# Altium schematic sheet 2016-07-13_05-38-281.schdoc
size 227 x 113 mm; SheetNumber: 1; SheetTotal: 1
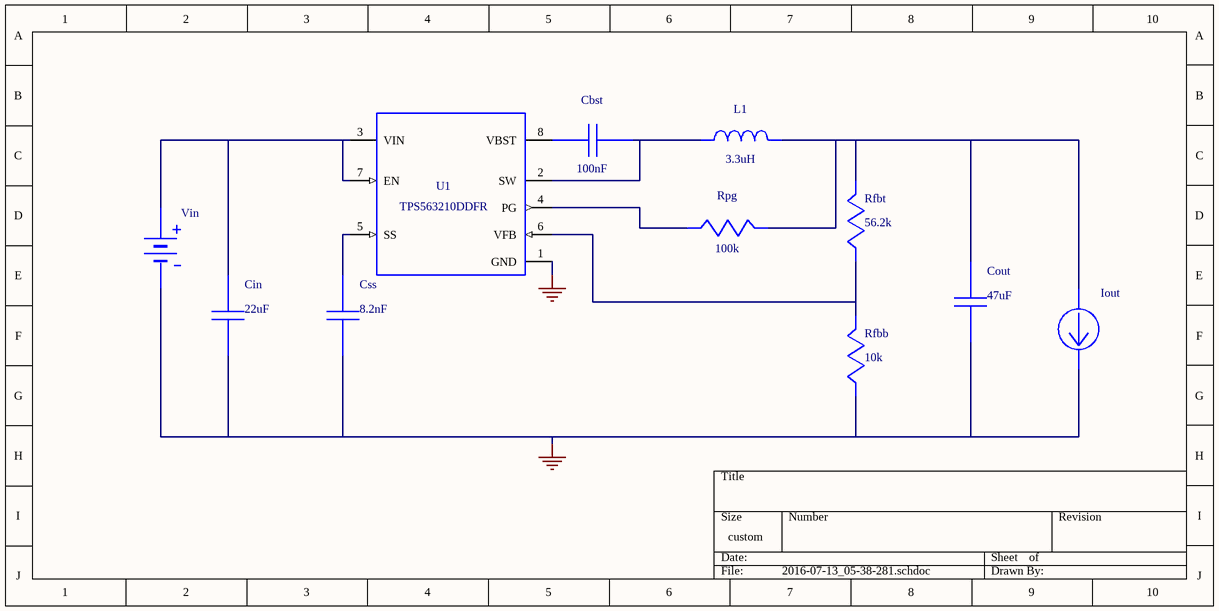
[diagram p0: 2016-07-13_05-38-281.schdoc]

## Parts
Cbst  value 100nF  (hidden comment: 08053C104KAT2A)
Cin  value 22uF  (hidden comment: GRM32ER61E226KE15L)
Cout  value 47uF  (hidden comment: C3216JB1A476M)
Css  value 8.2nF  (hidden comment: GRM033R61A822KA01D)
Iout  WB_CURRENT_LOAD  (value not drawn)
L1  value 3.3uH  (hidden comment: SRR6038-3R3Y)
Rfbb  value 10k  (hidden comment: CRCW040210K0FKED)
Rfbt  value 56.2k  (hidden comment: CRCW040256K2FKED)
Rpg  value 100k  (hidden comment: CRCW0402100KFKED)
U1  TPS563210DDFR
Vin  WB_BATTERY  (value not drawn)

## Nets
0: Cin.2 Cout.2 Css.2 Iout.2(-) Rfbb.2 U1.1(GND) Vin.2(-)
NetCbst_1: Cbst.1 L1.1 U1.2(SW)
NetCbst_2: Cbst.2 U1.8(VBST)
NetCin_1: Cin.1 U1.3(VIN) U1.7(EN) Vin.1(+)
NetCout_1: Cout.1 Iout.1(+) L1.2 Rfbt.1 Rpg.1
NetCss_1: Css.1 U1.5(SS)
NetRfbb_1: Rfbb.1 Rfbt.2 U1.6(VFB)
NetRpg_2: Rpg.2 U1.4(PG)

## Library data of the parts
Cbst = 08053C104KAT2A: Manufacturer Name: AVX
Cin = GRM32ER61E226KE15L: GRM32ER61E226KE1; Manufacturer Name: MuRata
Cout = C3216JB1A476M: Manufacturer Name: TDK
Css = GRM033R61A822KA01D: GRM033R61A822KA0; Manufacturer Name: MuRata
L1 = SRR6038-3R3Y: Manufacturer Name: Bourns
Rfbb = CRCW040210K0FKED: Manufacturer Name: Vishay-Dale
Rfbt = CRCW040256K2FKED: Manufacturer Name: Vishay-Dale
Rpg = CRCW0402100KFKED: Manufacturer Name: Vishay-Dale
U1 = TPS563210DDFR: Manufacturer Name: Texas Instruments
